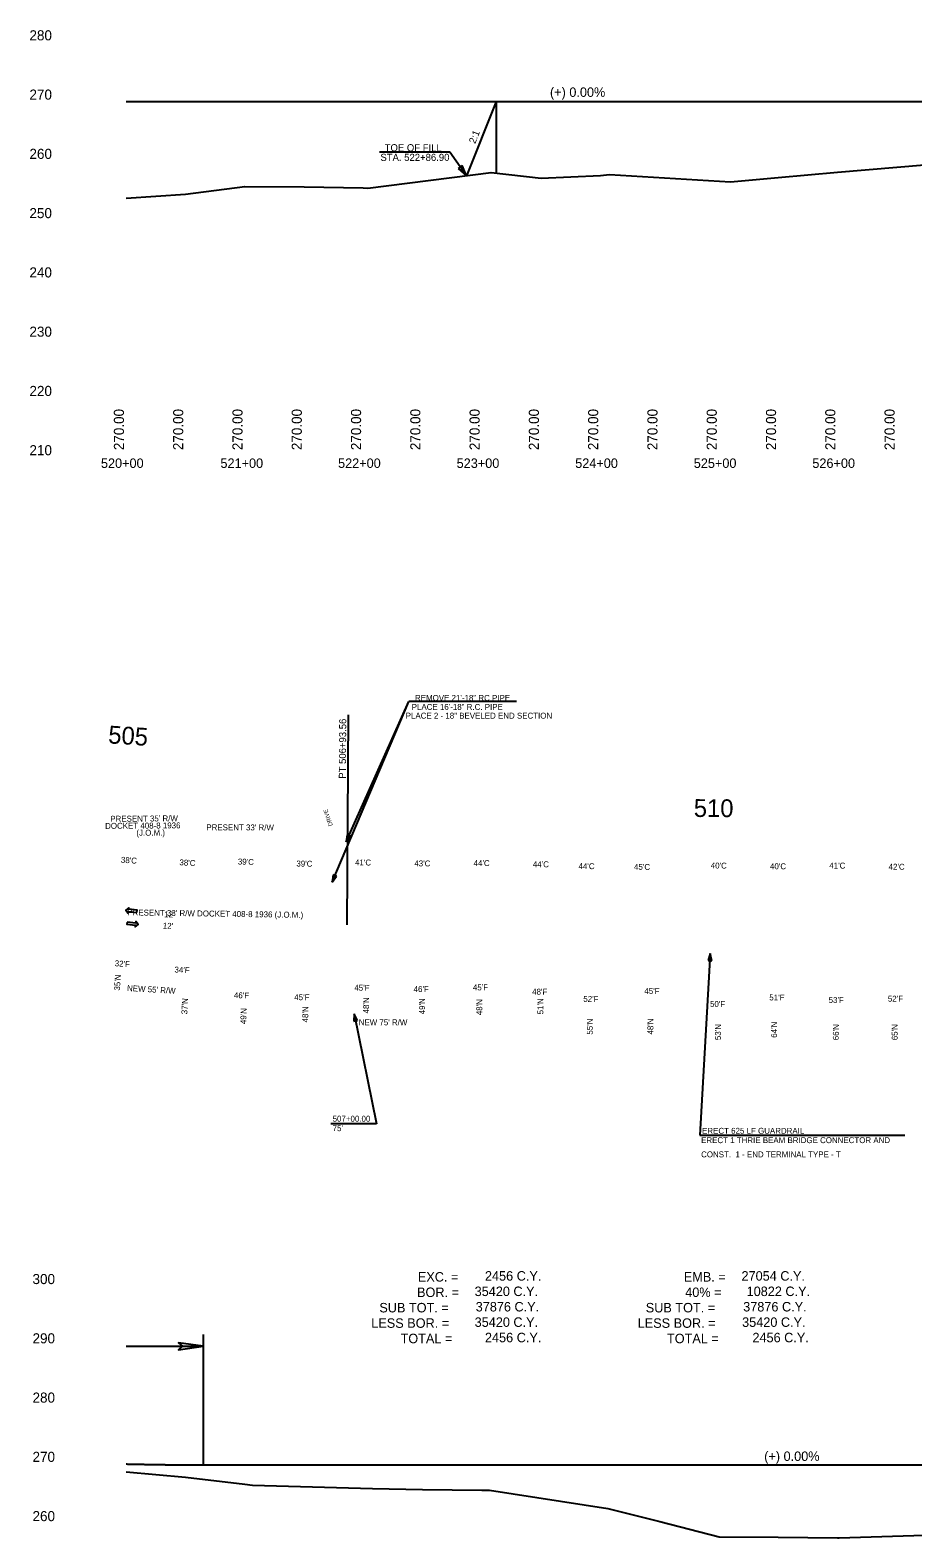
# Model space of a CAD drawing. Extents: x 48556 to 51363, y 45290 to 53458.
# Drawn here: x 49107 to 49851, y 48061 to 49333 of the extents above; entities that cross this region are included whole.
import ezdxf

# ---------------------------------------------------------------- set-up
doc = ezdxf.new("R2010")
doc.units = 0
for name, color, linetype in [('Level 1', 7, 'Continuous'), ('Level 14', 7, 'Continuous'), ('Level 19', 7, 'Continuous'), ('Level 20', 7, 'Continuous'), ('Level 24', 7, 'Continuous'), ('Level 27', 7, 'Continuous'), ('Level 29', 7, 'Continuous'), ('Level 33', 7, 'Continuous'), ('Level 40', 7, 'Continuous'), ('Level 41', 7, 'Continuous'), ('Level 42', 7, 'Continuous'), ('Level 43', 7, 'Continuous'), ('Level 45', 7, 'Continuous'), ('Level 48', 7, 'Continuous'), ('Level 6', 7, 'Continuous'), ('Level 8', 7, 'Continuous')]:
    doc.layers.add(name, color=color, linetype=linetype)

msp = doc.modelspace()

# ---------------------------------------------------------------- linework, layer by layer
at = {"layer": 'Level 1'}
msp.add_lwpolyline([(49252.9, 48222.9), (49232.1, 48225.8), (49235.3, 48222.9), (49232.1, 48219.9)], close=True, dxfattribs=at)
at = {"layer": 'Level 14'}
for points in [[(49197, 48588.9), (49197.2, 48590.8), (49189.9, 48591.6), (49190, 48592.8), (49187.5, 48590.8), (49189.5, 48588.3), (49189.7, 48589.6)], [(49188.7, 48580.8), (49188.5, 48578.9), (49195.8, 48578.1), (49195.6, 48576.8), (49198.1, 48578.8), (49196.1, 48581.3), (49196, 48580)]]:
    msp.add_lwpolyline(points, close=True, dxfattribs=at)
at = {"layer": 'Level 19'}
msp.add_line((49374.2, 48578.4), (49375.4, 48755.6), dxfattribs=at)
at = {"layer": 'Level 24'}
for p, q in [((49471.4, 49219.1), (49467.8, 49216.5)), ((49467.8, 49216.5), (49474.8, 49210.4)), ((49474.8, 49210.4), (49471.4, 49219.1)), ((49374.4, 48654.5), (49373.4, 48648.4)), ((49373.4, 48648.4), (49377.2, 48653.3)), ((49377.2, 48653.3), (49374.4, 48654.5)), ((49362.6, 48620.5), (49361.6, 48614.4)), ((49361.6, 48614.4), (49365.4, 48619.4)), ((49365.4, 48619.4), (49362.6, 48620.5)), ((49680.5, 48554.2), (49678.7, 48548.3)), ((49678.7, 48548.3), (49681.7, 48548.1)), ((49681.7, 48548.1), (49680.5, 48554.2)), ((49380.2, 48503.4), (49379.9, 48497.2)), ((49379.9, 48497.2), (49382.9, 48497.8)), ((49382.9, 48497.8), (49380.2, 48503.4))]:
    msp.add_line(p, q, dxfattribs=at)
at = {"layer": 'Level 27'}
for p, q in [((49680.5, 48554.2), (49671.6, 48401.1)), ((49671.6, 48401.1), (49844.7, 48401.1))]:
    msp.add_line(p, q, dxfattribs=at)
at = {"layer": 'Level 33'}
for p, q in [((49380.2, 48503.4), (49399.1, 48410.6)), ((49399.1, 48410.6), (49360.6, 48410.6))]:
    msp.add_line(p, q, dxfattribs=at)
at = {"layer": 'Level 40'}
for points in [[(49187.9, 49191.5), (49237.9, 49194.9), (49287.9, 49201.4), (49337.9, 49200.9), (49387.9, 49200.1), (49391.8, 49200), (49495.7, 49213), (49537.9, 49208.2), (49587.9, 49210.7), (49595.6, 49211.5), (49697.6, 49205.2), (49737.9, 49208.8), (49787.9, 49213.5), (49837.9, 49217.7), (49887.9, 49221.7)], [(49187.9, 48117.1), (49237.9, 48112.6), (49287.9, 48106.7), (49294.5, 48105.9), (49395.5, 48102.9), (49437.9, 48102.2), (49487.9, 48101.6), (49494.3, 48101.6), (49594.2, 48086.2), (49637.9, 48075), (49687.9, 48062.1), (49737.9, 48061.9), (49787.9, 48061.3), (49789.2, 48061.3), (49897.1, 48064.8)]]:
    msp.add_lwpolyline(points, dxfattribs=at)
at = {"layer": 'Level 41'}
for p, q in [((49252.9, 48232.9), (49252.9, 48122.9)), ((49187.9, 48222.9), (49252.9, 48222.9))]:
    msp.add_line(p, q, dxfattribs=at)
at = {"layer": 'Level 45'}
for p, q in [((49187.9, 49272.9), (49499.9, 49272.9)), ((49499.9, 49272.9), (49474.8, 49210.4)), ((49499.9, 49272.9), (49499.9, 49212.5)), ((49499.9, 49272.9), (50687.9, 49272.9)), ((49460.8, 49230.2), (49401.4, 49230.2)), ((49474.8, 49210.4), (49460.8, 49230.2)), ((49252.9, 48122.9), (50399.9, 48122.9))]:
    msp.add_line(p, q, dxfattribs=at)
msp.add_spline([(49187.9, 48123.7), (49189.2, 48123.6), (49190.5, 48123.6), (49191.8, 48123.6), (49193.1, 48123.6), (49194.4, 48123.5), (49195.7, 48123.5), (49197, 48123.5), (49198.3, 48123.4), (49199.6, 48123.4), (49200.9, 48123.4), (49202.2, 48123.4), (49203.5, 48123.3), (49204.8, 48123.3), (49206.1, 48123.3), (49207.4, 48123.3), (49208.7, 48123.2), (49210, 48123.2), (49211.3, 48123.2), (49212.6, 48123.2), (49213.9, 48123.2), (49215.2, 48123.1), (49216.5, 48123.1), (49217.8, 48123.1), (49219.1, 48123.1), (49220.4, 48123.1), (49221.7, 48123), (49223, 48123), (49224.3, 48123), (49225.6, 48123), (49226.9, 48123), (49228.2, 48123), (49229.5, 48123), (49230.8, 48122.9), (49232.1, 48122.9), (49233.4, 48122.9), (49234.7, 48122.9), (49236, 48122.9), (49237.3, 48122.9), (49238.6, 48122.9), (49239.9, 48122.9), (49241.2, 48122.9), (49242.5, 48122.9), (49243.8, 48122.9), (49245.1, 48122.9), (49246.4, 48122.9), (49247.7, 48122.9), (49249, 48122.9), (49250.3, 48122.9), (49251.6, 48122.9), (49252.9, 48122.9)], degree=3, dxfattribs=at)
at = {"layer": 'Level 6'}
for p in [(49361.6, 48614.4), (49373.4, 48648.4), (49517.2, 48766.9)]:
    msp.add_line(p, (49426.3, 48766.9), dxfattribs=at)

# ---------------------------------------------------------------- texts
at = {"layer": 'Level 1'}
for s, rotation, p in [(' DOCKET 408-8 1936 ', 0.4075, (49168.3, 48659.4)), ("PRESENT 35' R/W", 0.4075, (49174.5, 48665.4)), ("PRESENT 33' R/W ", 359.8723, (49255.5, 48658.2)), ('(J.O.M.)', 0.4075, (49196.5, 48653.6)), ("PRESENT 33' R/W DOCKET 408-8 1936 (J.O.M.)", 359.1607, (49188.8, 48586.5))]:
    msp.add_text(s, height=5, rotation=rotation, dxfattribs=at).set_placement(p)
for s, p in [('EXC. =', (49433.9, 48277.5)), (' 2456 C.Y.', (49487.5, 48278.3)), ('EMB. =', (49658.2, 48277.5)), (' 27054 C.Y.', (49703.9, 48278.3)), ('BOR. =', (49433.2, 48264.5)), (' 35420 C.Y.', (49478.8, 48265.3)), ('40% =', (49659.4, 48264.5)), (' 10822 C.Y.', (49708.2, 48265.3)), ('SUB TOT. =', (49401.4, 48251.5)), (' 37876 C.Y.', (49479.7, 48252.3)), ('SUB TOT. =', (49626.1, 48251.5)), (' 37876 C.Y.', (49705.3, 48252.3)), ('LESS BOR. =', (49394.6, 48238.5)), (' 35420 C.Y.', (49478.8, 48239.3)), ('LESS BOR. =', (49619.3, 48238.5)), (' 35420 C.Y.', (49704.4, 48239.3)), ('TOTAL =', (49419.3, 48225.5)), (' 2456 C.Y.', (49487.5, 48226.3)), ('TOTAL =', (49644, 48225.5)), (' 2456 C.Y.', (49713.1, 48226.3))]:
    msp.add_text(s, height=8, dxfattribs=at).set_placement(p)
at = {"layer": 'Level 19'}
for s, height, rotation, p in [('PT 506+93.56', 6, 89.6334, (49373.2, 48701.7)), ('505', 15, 356.2461, (49172.4, 48731.6)), ('510', 15, 359.6334, (49666.6, 48669.5))]:
    msp.add_text(s, height=height, rotation=rotation, dxfattribs=at).set_placement(p)
at = {"layer": 'Level 20'}
for p in [(49219.9, 48584.9), (49218.7, 48575.3)]:
    msp.add_text("12'", height=5, rotation=357.8501, dxfattribs=at).set_placement(p)
at = {"layer": 'Level 27'}
for s, p in [('ERECT 1 THRIE BEAM BRIDGE CONNECTOR AND ', (49672.8, 48394.3)), ('ERECT 625 LF GUARDRAIL', (49673.6, 48402.2)), ('CONST.  1 - END TERMINAL TYPE - T', (49672.8, 48382.3))]:
    msp.add_text(s, height=5, dxfattribs=at).set_placement(p)
at = {"layer": 'Level 29'}
for s, p in [('PLACE 16\'-18" R.C. PIPE', (49428.7, 48759.8)), (' PLACE 2 - 18" BEVELED END SECTION', (49421.8, 48752.4))]:
    msp.add_text(s, height=5, dxfattribs=at).set_placement(p)
at = {"layer": 'Level 33'}
for s, rotation, p in [("NEW 55' R/W", 356.5816, (49188.5, 48522.7)), ("NEW 75' R/W", 359.7811, (49384, 48493.8))]:
    msp.add_text(s, height=5, rotation=rotation, dxfattribs=at).set_placement(p)
for s, p in [('507+00.00', (49362, 48412.4)), ("75'", (49362, 48404.4))]:
    msp.add_text(s, height=5, dxfattribs=at).set_placement(p)
at = {"layer": 'Level 41'}
for p in [(49545.3, 49276.9), (49726, 48126.2)]:
    msp.add_text('(+) 0.00%', height=8, dxfattribs=at).set_placement(p)
at = {"layer": 'Level 42'}
for s, height, p in [('280', 8.5, (49106.3, 49324.6)), ('270', 8.5, (49106.3, 49274.6)), ('260', 8.5, (49106.3, 49224.6)), ('250', 8.5, (49106.3, 49174.6)), ('240', 8.5, (49106.3, 49124.6)), ('230', 8.5, (49106.3, 49074.6)), ('220', 8.5, (49106.3, 49024.6)), ('210', 8.5, (49106.3, 48974.6)), ('520+00', 8, (49166.6, 48963.9)), ('521+00', 8, (49267.4, 48963.9)), ('522+00', 8, (49366.6, 48963.9)), ('523+00', 8, (49466.6, 48963.9)), ('524+00', 8, (49566.6, 48963.9)), ('525+00', 8, (49666.6, 48963.9)), ('526+00', 8, (49766.6, 48963.9)), ('300', 8.5, (49108.9, 48275.4)), ('290', 8.5, (49108.9, 48225.4)), ('280', 8.5, (49108.9, 48175.4)), ('270', 8.5, (49108.9, 48125.4)), ('260', 8.5, (49108.9, 48075.4))]:
    msp.add_text(s, height=height, dxfattribs=at).set_placement(p)
at = {"layer": 'Level 43'}
for p in [(49186, 48978.9), (49236, 48978.9), (49286, 48978.9), (49336, 48978.9), (49386, 48978.9), (49436, 48978.9), (49486, 48978.9), (49536, 48978.9), (49586, 48978.9), (49636, 48978.9), (49686, 48978.9), (49736, 48978.9), (49786, 48978.9), (49836, 48978.9)]:
    msp.add_text('270.00', height=8.5, rotation=90, dxfattribs=at).set_placement(p)
at = {"layer": 'Level 45'}
msp.add_text('2:1', height=6, rotation=68.0994, dxfattribs=at).set_placement((49482.2, 49236.9))
for s, p in [('TOE OF FILL ', (49405.9, 49231)), ('STA. 522+86.90', (49402.3, 49222.9))]:
    msp.add_text(s, height=6, dxfattribs=at).set_placement(p)
at = {"layer": 'Level 48'}
for s, rotation, p in [("38'C", 356.2461, (49183.3, 48630.9)), ("38'C", 357.1211, (49232.7, 48628.7)), ("39'C", 357.9961, (49282, 48629.4)), ("39'C", 358.8711, (49331.4, 48627.7)), ("41'C", 359.6334, (49380.9, 48628.6)), ("43'C", 359.6334, (49430.9, 48627.8)), ("44'C", 359.6334, (49480.9, 48628.1)), ("44'C", 359.6334, (49530.9, 48627.1)), ("44'C", 359.6334, (49569.4, 48625.5)), ("45'C", 359.6334, (49616.2, 48624.9)), ("40'C", 359.6334, (49680.9, 48626)), ("40'C", 359.6334, (49730.9, 48625.4)), ("41'C", 359.6334, (49780.9, 48626)), ("42'C", 359.6334, (49830.9, 48625)), ("32'F", 356.2461, (49178.1, 48543.6)), ("35'N", 86.2461, (49182.6, 48522.9)), ("34'F", 357.1211, (49228.5, 48538.3)), ("45'F", 359.6334, (49380.3, 48522.9)), ("46'F", 359.6334, (49430.3, 48521.8)), ("45'F", 359.6333, (49480.3, 48523.2)), ("48'F", 359.6334, (49530.3, 48519.6)), ("45'F", 359.6334, (49624.9, 48520.2)), ("37'N", 87.1211, (49239.4, 48502.9)), ("46'F", 357.9961, (49278.7, 48516.7)), ("45'F", 358.8711, (49329.6, 48515)), ("48'N", 89.6334, (49392.7, 48503.7)), ("49'N", 89.6334, (49439.9, 48503)), ("48'N", 89.6333, (49488.2, 48502.2)), ("51'N", 89.6334, (49539.7, 48502.9)), ("52'F", 359.6334, (49573.4, 48513.5)), ("50'F", 359.6334, (49680.3, 48509.2)), ("51'F", 359.6334, (49730.3, 48514.7)), ("53'F", 359.6333, (49780.3, 48512.6)), ("52'F", 359.6334, (49830.3, 48513.7)), ("49'N", 87.9961, (49289.1, 48494.6)), ("48'N", 88.8711, (49341.3, 48496.1)), ("55'N", 89.6334, (49581.4, 48485.8)), ("48'N", 89.6334, (49632.5, 48485.9)), ("53'N", 89.6334, (49689.5, 48481.2)), ("64'N", 89.6334, (49736.8, 48483.2)), ("66'N", 89.6333, (49788.9, 48481.1)), ("65'N", 89.6334, (49838.5, 48481.1))]:
    msp.add_text(s, height=5, rotation=rotation, dxfattribs=at).set_placement(p)
at = {"layer": 'Level 6'}
msp.add_text('REMOVE 21\'-18" RC PIPE', height=5, dxfattribs=at).set_placement((49431.5, 48767.4))
at = {"layer": 'Level 8'}
msp.add_text('DRIVE', height=3.5, rotation=108.8976, dxfattribs=at).set_placement((49362.2, 48662.4))

doc.saveas('drawing.dxf')
